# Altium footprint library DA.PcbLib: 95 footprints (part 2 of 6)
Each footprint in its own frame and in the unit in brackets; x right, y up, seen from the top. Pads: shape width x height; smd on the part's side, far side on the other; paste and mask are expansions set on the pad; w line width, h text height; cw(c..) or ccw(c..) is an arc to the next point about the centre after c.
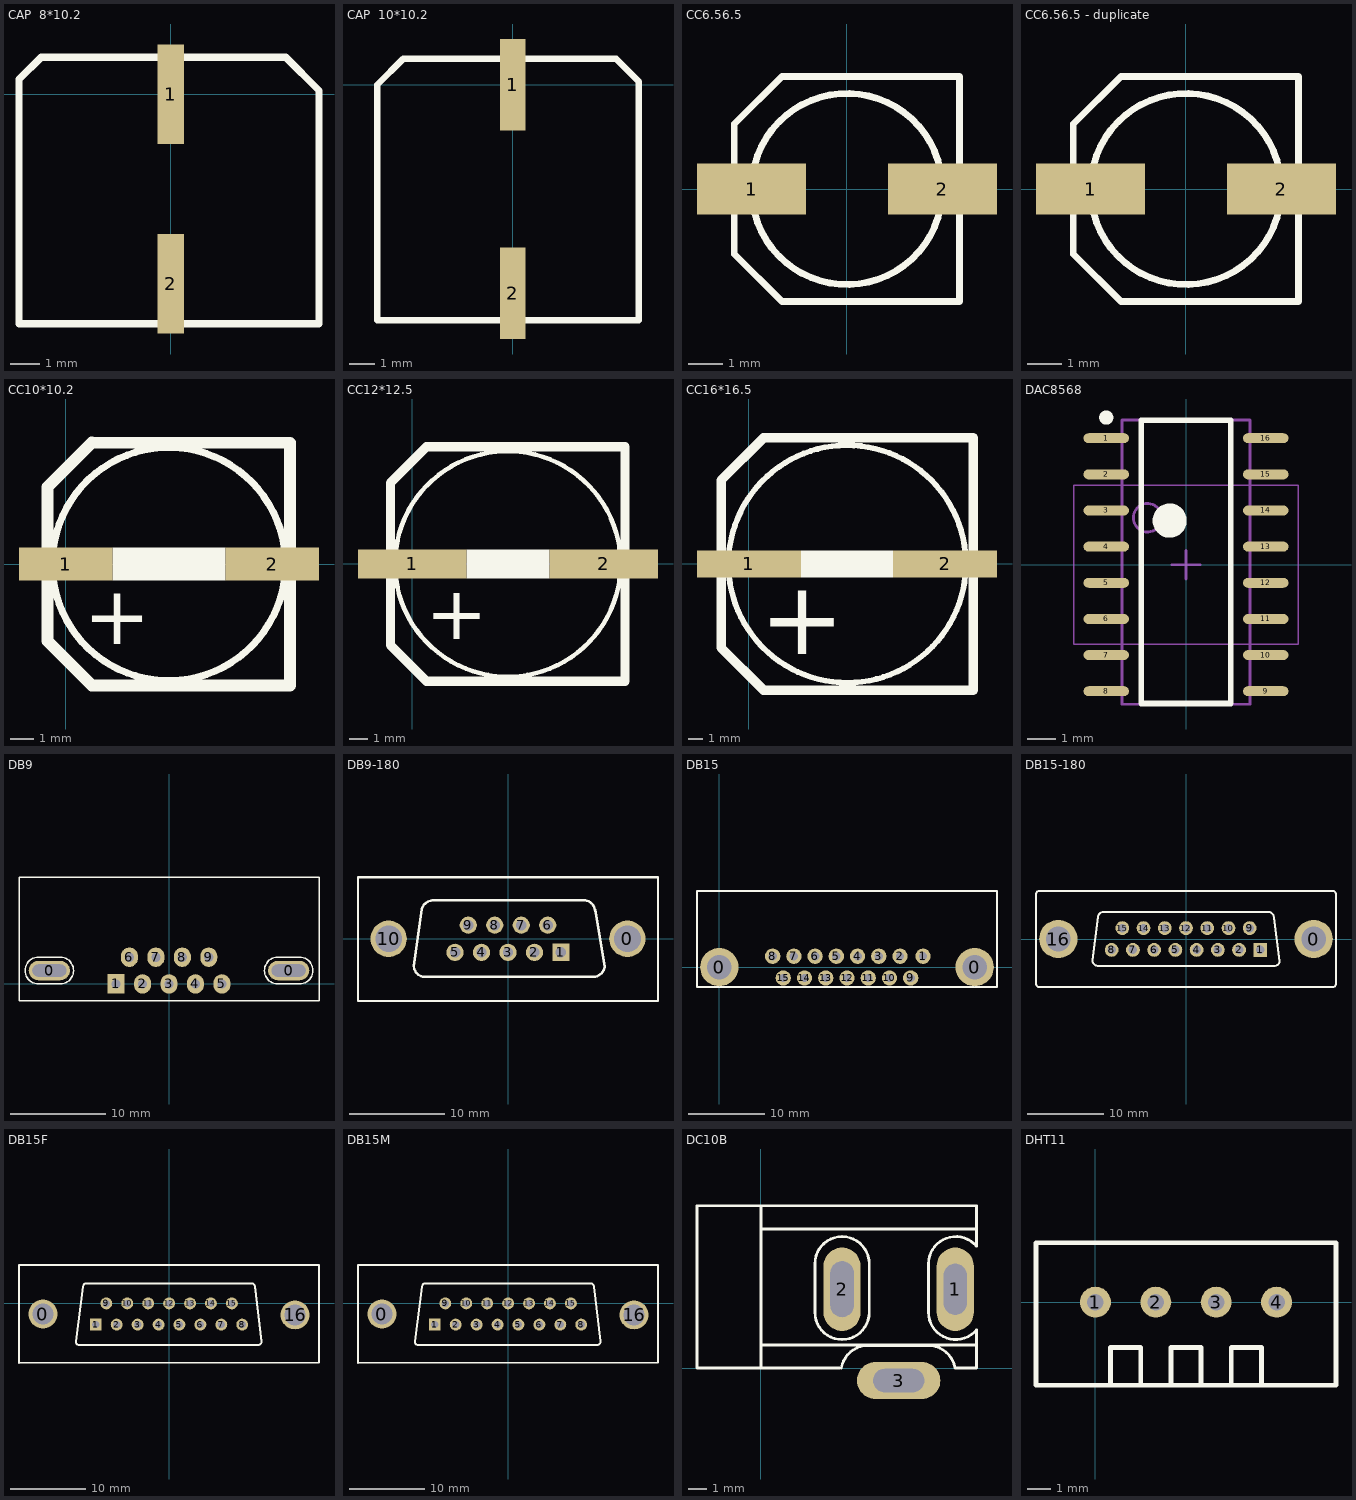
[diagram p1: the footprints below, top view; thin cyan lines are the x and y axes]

## CAP  8*10.2 [mm]
pads (2):
  rect 0.9x3.4 smd: 1(0,0) 2(0,-6.5)
Top Overlay:
  lines w0.254: -5.207,-7.874 -5.207,0.508 -4.445,1.27 3.937,1.27 5.08,0.127 5.08,-7.874 -5.207,-7.874

## CAP  10*10.2 [mm]
pads (2):
  rect 1x3.6 smd: 1(0,-0.001) 2(0,-8.2)
Top Overlay:
  lines w0.254: -5.334,-9.271 -5.334,-8.128 -5.334,0 -4.318,1.016 4.064,1.016 4.953,0.127 4.953,-8.128 4.953,-9.271 3.81,-9.271 -3.937,-9.271 -5.334,-9.271

## CC6.56.5 [mm]
pads (2):
  rect 3.2x1.5 smd: 1(-2.794,0) 2(2.8,0)
Top Overlay:
  circle w0.2: c0,0 r2.8
  lines w0.2: -3.302,-1.905 -1.905,-3.302 3.302,-3.302 3.302,3.302 -1.905,3.302 -3.302,1.905 -3.302,-1.905

## CC6.56.5 - duplicate [mm]
pads (2):
  rect 3.2x1.5 smd: 1(-2.794,0) 2(2.8,0)
Top Overlay:
  circle w0.2: c0,0 r2.8
  lines w0.2: -3.302,-1.905 -3.302,1.905 -1.905,3.302 3.302,3.302 3.302,-3.302 -1.905,-3.302 -3.302,-1.905

## CC10*10.2 [mm]
pads (2):
  rect 4x1.4 smd: 1(0,0) 2(8.86,0)
Top Overlay:
  circle w0.305: c4.422,0 r5
  rectangle: 2.006,-0.701 6.849,0.707
  lines w0.508: 1.12,5.203 -0.778,3.306 -0.778,-3.304 1.12,-5.201 9.62,-5.201 9.62,5.2 1.123,5.2
  text "+" at 0.78,-3.44 h2.5

## CC12*12.5 [mm]
pads (2):
  rect 6x1.6 smd: 1(0,0) 2(10.625,0)
Top Overlay:
  circle w0.254: c5.303,0 r6.25
  rectangle: 3.019,-0.8 7.601,0.8
  lines w0.508: -1.202,-4.498 -1.202,4.494 0.797,6.493 0.799,6.495 11.797,6.495 11.797,-6.499 0.799,-6.499 -1.202,-4.498
  text "+" at 0.75,-4.168 h3

## CC16*16.5 [mm]
pads (2):
  rect 7x1.8 smd: 1(0,0) 2(13.215,0)
Top Overlay:
  rectangle: 3.503,-0.9 9.696,0.914
  lines w0.381: 14.301,2.24 ccw(c6.62,0.001) 14.315,2.19
  lines w0.635: 15.122,-8.499 15.123,-8.5 ; 15.122,8.496 15.123,8.497 ; 15.123,-8.5 15.123,8.497 ; 15.123,-8.5 0.981,-8.5 -1.877,-5.642 -1.877,5.638 0.981,8.497 15.123,8.497
  text "+" at 0.729,-6.087 h5

## DAC8568 [mm]
height 1.2
pads (16):
  oval 1.6x0.35 smd: 1(-2.8,4.445) 2(-2.8,3.175) 3(-2.8,1.905) 4(-2.8,0.635) 5(-2.8,-0.635) 6(-2.8,-1.905) 7(-2.8,-3.175) 8(-2.8,-4.445) 9(2.8,-4.445) 10(2.8,-3.175) 11(2.8,-1.905) 12(2.8,-0.635) 13(2.8,0.635) 14(2.8,1.905) 15(2.8,3.175) 16(2.8,4.445)
Top Overlay:
  circle w0.6: c-0.575,1.55 r0.3
  circle w0.25: c-2.8,5.17 r0.125
  lines w0.2: -1.575,-4.877 1.575,-4.877 1.575,5.08 -1.575,5.08 -1.575,-4.877
Mechanical 13:
  circle w0.1: c-1.35,1.65 r0.5
  lines w0.1: -2.25,-4.902 2.25,-4.902 2.25,5.08 -2.25,5.08 -2.25,-4.902
Mechanical 15:
  lines w0.05: -3.95,-2.8 3.95,-2.8 3.95,2.8 -3.95,2.8 -3.95,-2.8
  lines w0.1: -0.5,0 0.5,0 ; 0,-0.5 0,0.5
3D body: height 1.2, standoff 0.1, extent -2.261,-4.902 2.261,5.08

## DB9 [mil]
pads (11):
  oval 170x80 hole 50 slot 140 at 0 deg: 0(-493,55) 0(493,55)
  rect 70x80 hole 38: 1(-218,0)
  oval 70x80 hole 38: 2(-109,0) 3(0,0) 4(109,0) 5(218,0) 6(-163,110) 7(-54,110) 8(55,110) 9(164,110)
Top Overlay:
  lines w6: -618,-70 -618,440 618,440 618,-70 -618,-70 ; -538,0 cw(c-538,55) -538,110 -448,110 cw(c-448,55) -448,0 -538,0 ; 448,0 cw(c448,55) 448,110 538,110 cw(c538,55) 538,0 448,0

## DB9-180 [mm]
pads (11):
  round 3.81 hole 2.794: 0(12.495,0) 10(-12.495,0)
  rect 1.8x1.8 hole 1.09: 1(5.54,-1.42)
  round 1.8 hole 1.09: 2(2.77,-1.42) 3(0,-1.42) 4(-2.77,-1.42) 5(-5.54,-1.42) 6(4.157,1.42) 7(1.385,1.42) 8(-1.385,1.42) 9(-4.157,1.42)
Top Overlay:
  lines w0.203: -15.697,-6.502 15.697,-6.502 15.697,6.452
  lines w0.254: -15.697,-6.502 -15.697,6.452 15.697,6.452 ; -8.933,-3.977 cw(c-8.623,-2.783) -9.855,-2.845 -9.032,3.091 cw(c-7.838,2.781) -7.899,4.013 ; -8.914,-3.976 8.975,-3.976 ; -7.955,4.026 8.076,4.026 ; 8.077,4.013 cw(c7.922,2.825) 9.119,2.876 ; 8.972,-3.989 ccw(c8.921,-2.791) 10.109,-2.946 9.119,3.048

## DB15 [mm]
pads (17):
  round 5 hole 3.18: 0(0,0) 0(33.32,0)
  round 2 hole 1.09: 1(26.58,1.42) 2(23.58,1.42) 3(20.81,1.42) 4(18.04,1.42) 5(15.27,1.42) 6(12.5,1.42) 7(9.73,1.42) 8(6.96,1.42) 9(24.965,-1.42) 10(22.195,-1.42) 11(19.425,-1.42) 12(16.665,-1.42) 13(13.885,-1.42) 14(11.115,-1.42) 15(8.345,-1.42)
Top Overlay:
  lines w0.254: -2.91,-2.6 36.23,-2.6 36.23,9.93 -2.91,9.93 -2.91,-2.6

## DB15-180 [mm]
pads (17):
  round 5 hole 3.2: 0(16.66,0) 16(-16.66,0)
  rect 1.8x1.8 hole 1.09: 1(9.697,-1.42)
  round 1.8 hole 1.09: 2(6.926,-1.42) 3(4.156,-1.42) 4(1.385,-1.42) 5(-1.385,-1.42) 6(-4.156,-1.42) 7(-6.926,-1.42) 8(-9.697,-1.42) 9(8.31,1.42) 10(5.54,1.42) 11(2.77,1.42) 12(0,1.42) 13(-2.77,1.42) 14(-5.54,1.42) 15(-8.31,1.42)
Top Overlay:
  lines w0.254: -19.57,-5.83 -19.57,5.881 ; -19.56,5.88 cw(c-19.126,5.842) -19.176,6.275 19.176,6.275 ; -19.559,-5.892 ccw(c-19.126,-5.842) -19.164,-6.276 ; -19.125,-6.275 19.176,-6.275 ccw(c19.126,-5.842) 19.56,-5.88 ; -12.22,-2.75 -11.5,2.87 cw(c-10.744,2.768) -10.744,3.531 10.856,3.524 ; -12.217,-2.743 ccw(c-11.455,-2.743) -11.557,-3.499 11.608,-3.499 ; 10.82,3.524 cw(c10.718,2.769) 11.481,2.769 ; 11.5,2.75 12.22,-2.87 ; 11.608,-3.506 ccw(c11.557,-2.845) 12.208,-2.716 ; 19.164,6.276 cw(c19.126,5.842) 19.559,5.892 ; 19.57,-5.881 19.57,5.881

## DB15F [mil]
pads (17):
  round 150 hole 110: 0(-657,-55) 16(656,-60)
  rect 62x62 hole 38: 1(-382,-110)
  round 62 hole 38: 2(-273,-110) 3(-164,-110) 4(-55,-110) 5(54,-110) 6(163,-110) 7(272,-110) 8(381,-110) 9(-327,0) 10(-218,0) 11(-109,0) 12(0,0) 13(109,0) 14(218,0) 15(327,0)
Top Overlay:
  lines w8: -782,-310 781,-310 781,200
  lines w10: -782,-310 -782,200 781,200 ; -485.43,-200 ccw(c-468.59,-200) -467.6,-216.81 464.03,-216.81 ; -485.43,-196.85 -447.81,86.61 ; -447.81,87.01 cw(c-431,88) -431,104.84 ; -431,104.72 429.01,104.72 cw(c430,87.91) 446.84,87.91 481.81,-198.01 cw(c465,-199) 465,-215.84

## DB15M [mil]
pads (17):
  round 150 hole 110: 0(-657,-55) 16(656,-60)
  rect 62x62 hole 38: 1(-382,-110)
  round 62 hole 38: 2(-273,-110) 3(-164,-110) 4(-55,-110) 5(54,-110) 6(163,-110) 7(272,-110) 8(381,-110) 9(-327,0) 10(-218,0) 11(-109,0) 12(0,0) 13(109,0) 14(218,0) 15(327,0)
Top Overlay:
  lines w8: -782,-310 781,-310 781,200
  lines w10: -782,-310 -782,200 781,200 ; -485.43,-200 ccw(c-468.59,-200) -467.6,-216.81 ; -485.43,-196.85 -447.81,86.61 ; -466.01,-216.81 465,-215.84 ccw(c465,-199) 481.81,-198.01 ; -447.81,87.01 cw(c-431,88) -431,104.84 ; -431,104.72 429.01,104.72 cw(c430,87.91) 446.84,87.91 ; 446.84,86.61 481.81,-196.85

## DC10B [mil]
height 149.61
pads (3):
  oval 80x180 hole 50 slot 110 at 90 deg: 1(419.09,170)
  oval 80x180 hole 50 slot 120 at 90 deg: 2(175,170)
  oval 180x80 hole 50 slot 110 at 0 deg: 3(297.05,-26.85)
Top Overlay:
  lines w6: 0,50 465,50 ; 0,300 460.13,300 464.25,300 ; 5,350 -15,350 -137.8,350 -137.8,0 0,0 ; 169,0 0,0 ; 173.37,0.16 cw(c231,-10) 231,48.52 361,48.52 cw(c361,-10) 418.63,0.16 ; 420,0 465,0 465,80 ; 464.83,82.38 cw(c420,120) 361.48,120 361.48,225 cw(c420,225) 464.83,262.62 465,350 0,350 0,0 ; 233.52,225 ccw(c175,225) 116.48,225 116.48,120 ccw(c175,120) 233.52,120 233.52,225 ; 233.52,225 233.52,225

## DHT11 [mm]
pads (4):
  round 1.3 hole 0.7: 1(0,0) 2(2.54,0) 3(5.08,0) 4(7.62,0)
Top Overlay:
  lines w0.203: -2.5,-3.5 7.62,-3.5 10.12,-3.5 ; -2.5,-3.46 -2.5,0 -2.5,2.5 7.62,2.5 10.12,2.5 10.12,0 10.12,-3.46 ; 0.635,-3.5 0.635,-1.905 1.905,-1.905 1.905,-3.5 ; 3.175,-3.5 3.175,-1.905 4.445,-1.905 4.445,-3.5 ; 5.715,-3.5 5.715,-1.905 6.985,-1.905 6.985,-3.5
